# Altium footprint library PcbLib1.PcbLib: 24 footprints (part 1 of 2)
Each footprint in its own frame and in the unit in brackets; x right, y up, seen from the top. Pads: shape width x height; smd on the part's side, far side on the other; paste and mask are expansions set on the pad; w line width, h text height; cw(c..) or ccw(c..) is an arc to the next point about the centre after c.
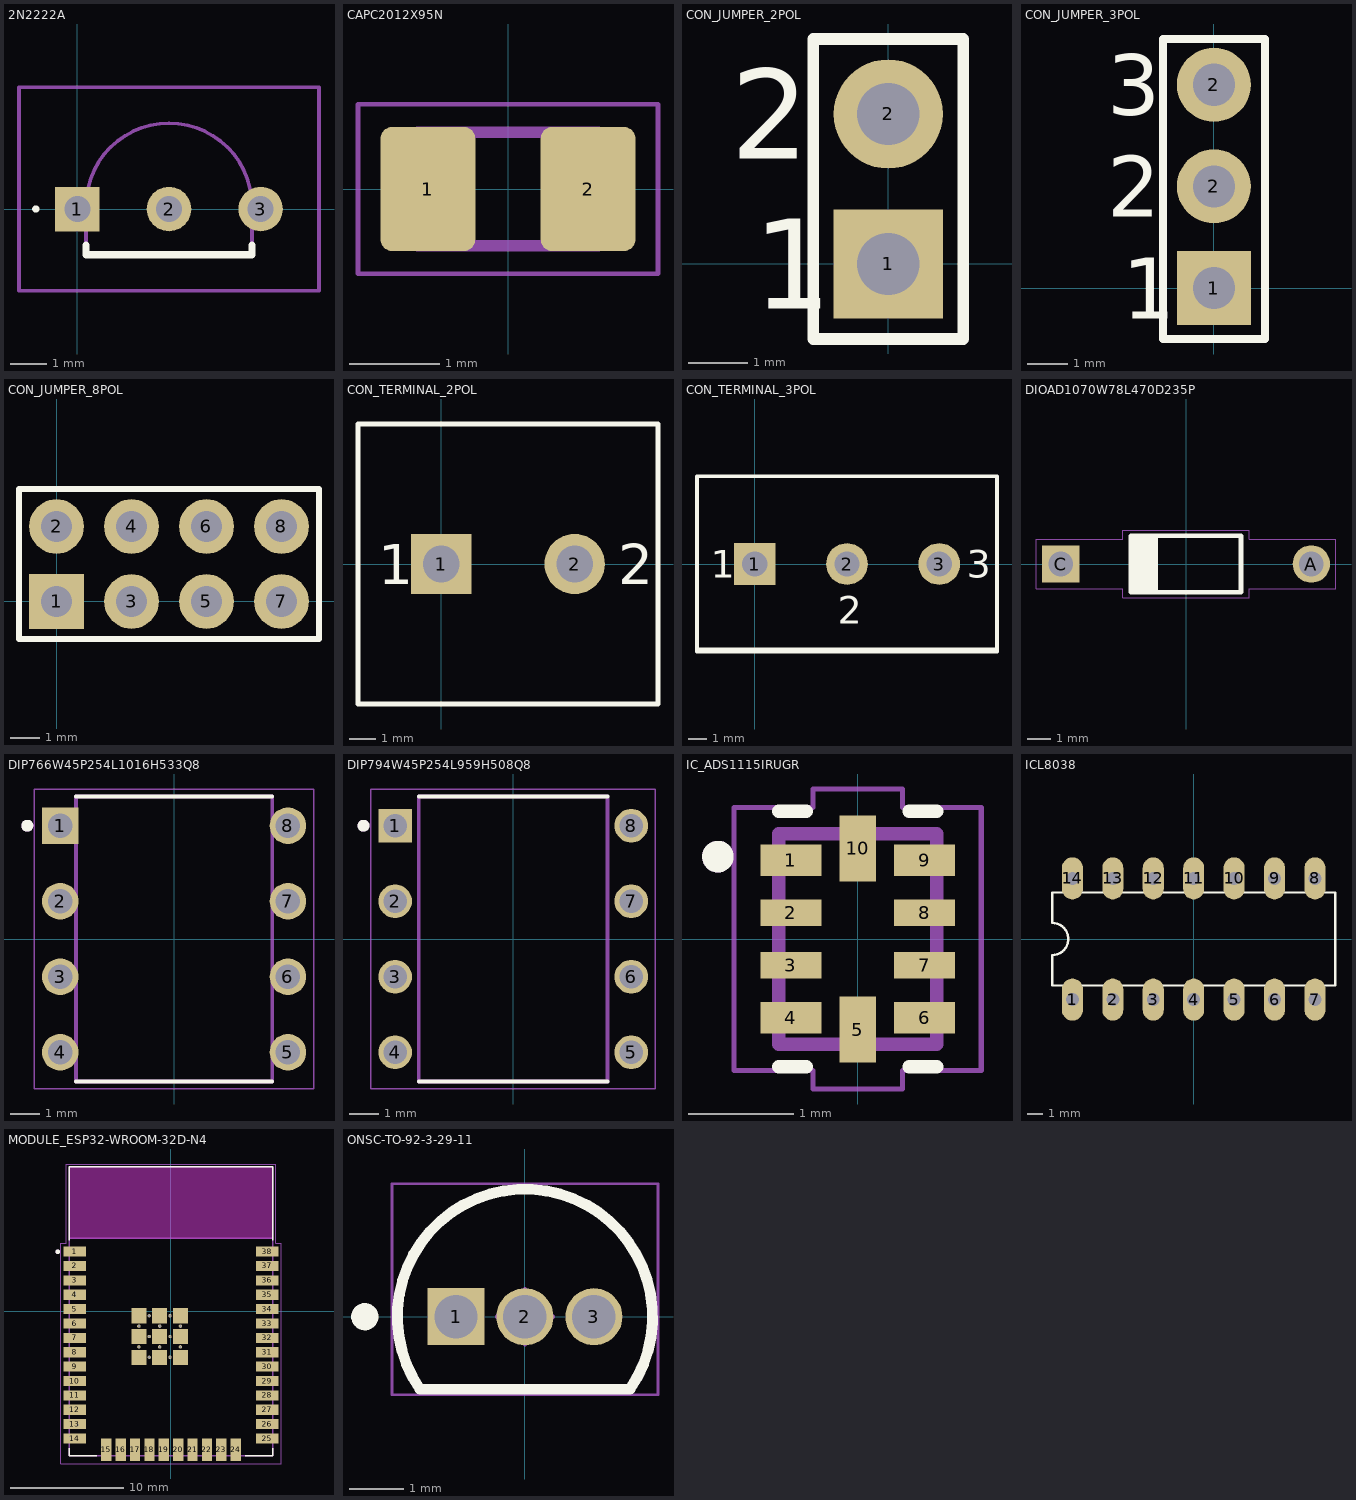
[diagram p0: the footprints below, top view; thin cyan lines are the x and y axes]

## 2N2222A [mm]
pads (3):
  rect 1.234x1.234 hole 0.72: 1(0,0)
  round 1.234 hole 0.72: 2(2.54,0) 3(5.08,0)
Top Overlay:
  lines w0.1: -1.2,0 cw(c-1.15,0) -1.1,0 cw(c-1.15,0) -1.2,0
  lines w0.2: 0.24,-1 0.24,-1.27 4.84,-1.27 4.84,-1
Mechanical 13:
  lines w0.1: 0.24,-1.27 0.24,0.08 cw(c2.54,0.08) 4.84,0.08 4.84,-1.27 0.24,-1.27
Mechanical 15:
  lines w0.1: -1.617,-2.27 -1.617,3.38 6.697,3.38 6.697,-2.27 -1.617,-2.27
3D body "2N2222A.stp": height 7.46, standoff -9.64, extent -0.2,-1.25 5.28,2.35

## CAPC2012X95N [mm]
pads (2):
  rrect25% 1.05x1.38 smd: 1(-0.888,0) 2(0.888,0)
Mechanical 13:
  lines w0.127: -1,-0.63 1,-0.63 1,0.63 -1,0.63 -1,-0.63
Mechanical 15:
  lines w0.05: -1.663,-0.94 1.663,-0.94 1.663,0.94 -1.663,0.94 -1.663,-0.94
3D body "step_temp.STEP": height 0.95, standoff 0, extent -1,-0.625 1,0.625

## CON_JUMPER_2POL [mm] "Jumper"
pads (2):
  rect 1.85x1.85 hole 1.05: 1(0,0)
  round 1.85 hole 1.05: 2(0,2.54)
Top Overlay:
  lines w0.2: -1.27,-1.27 1.27,-1.27 1.27,3.81 -1.27,3.81 -1.27,2.54 -1.27,-1.27
  text "1" at -2.286,-0.762 h1.52
  text "2" at -2.667,1.778 h1.52

## CON_JUMPER_3POL [mm] "Jumper"
pads (3):
  rect 1.85x1.85 hole 1.05: 1(0,0)
  round 1.85 hole 1.05: 2(0,2.54) 2(0,5.08)
Top Overlay:
  lines w0.2: -1.27,-1.27 1.27,-1.27 1.27,6.223 -1.27,6.223 -1.27,2.413 -1.27,-1.27
  text "3" at -2.667,4.318 h1.52
  text "1" at -2.286,-0.762 h1.52
  text "2" at -2.667,1.778 h1.52

## CON_JUMPER_8POL [mm] "Jumper"
pads (8):
  rect 1.85x1.85 hole 1.05: 1(0,0)
  round 1.85 hole 1.05: 2(0,2.54) 3(2.54,0) 4(2.54,2.54) 5(5.08,0) 6(5.08,2.54) 7(7.62,0) 8(7.62,2.54)
Top Overlay:
  lines w0.2: -1.27,-1.27 -1.27,3.81 8.89,3.81 8.89,-1.27 -1.27,-1.27

## CON_TERMINAL_2POL [mm] "Terminal Screw"
pads (2):
  rect 2.3x2.3 hole 1.4: 1(0,0)
  round 2.3 hole 1.4: 2(5.08,0)
Top Overlay:
  lines w0.2: -3.175,-5.334 -3.175,0 -3.175,5.334 8.255,5.334 8.255,-5.334 -3.175,-5.334
  text "2" at 6.731,-0.762 h1.52
  text "1" at -2.413,-0.762 h1.52

## CON_TERMINAL_3POL [mm] "Terminal Screw"
pads (3):
  rect 2.3x2.3 hole 1.4: 1(0,0)
  round 2.3 hole 1.4: 2(5.08,0) 3(10.16,0)
Top Overlay:
  lines w0.2: -3.048,-4.699 13.208,-4.699 ; -3.175,-4.826 -3.175,0 -3.175,4.826 13.335,4.826 13.335,-4.826 -3.175,-4.826
  text "3" at 11.684,-0.762 h1.52
  text "2" at 4.572,-3.302 h1.52
  text "1" at -2.413,-0.762 h1.52

## DIOAD1070W78L470D235P [mm]
pads (2):
  round 1.6 hole 1.05: A(5.35,0)
  rect 1.6x1.6 / inner round 1.6 / far side rect 1.6x1.6 hole 1.05: C(-5.35,0)
Top Overlay:
  region: -1.2,-1.202 -2.403,-1.202 -2.403,1.2 -1.2,1.2
  lines w0.2: -2.35,-1.2 -2.35,1.2 2.35,1.2 2.35,-1.2 -2.35,-1.2
Mechanical 15:
  lines w0.05: -6.4,-1.05 -6.4,1.05 -2.7,1.05 -2.7,1.45 2.7,1.45 2.7,1.05 6.4,1.05 6.4,-1.05 2.7,-1.05 2.7,-1.45 -2.7,-1.45 -2.7,-1.05 -6.4,-1.05
3D body "step_temp.STEP": height 2.7, standoff -21.05, extent -5.743,-1.35 5.743,1.35

## DIP766W45P254L1016H533Q8 [mm]
pads (8):
  rect 1.23x1.23 / inner round 1.23 / far side rect 1.23x1.23 hole 0.82: 1(-3.83,3.81)
  round 1.23 hole 0.82: 2(-3.83,1.27) 3(-3.83,-1.27) 4(-3.83,-3.81) 5(3.83,-3.81) 6(3.83,-1.27) 7(3.83,1.27) 8(3.83,3.81)
Top Overlay:
  circle w0.2: c-4.935,3.81 r0.1
  lines w0.127: -3.303,-4.795 3.303,-4.795 ; -3.303,4.795 3.303,4.795
Mechanical 13:
  circle w0.2: c-4.935,3.81 r0.1
  lines w0.127: -3.303,-4.795 3.303,-4.795 3.303,4.795 -3.303,4.795 -3.303,-4.795
Mechanical 15:
  lines w0.05: -4.695,-5.045 4.695,-5.045 4.695,5.045 -4.695,5.045 -4.695,-5.045
3D body "step_temp.STEP": height 5.33, standoff -3, extent -4.003,-4.94 4.003,4.94

## DIP794W45P254L959H508Q8 [mm]
pads (8):
  rect 1.13x1.13 / inner round 1.13 / far side rect 1.13x1.13 hole 0.78 mask+0.102: 1(-3.97,3.81)
  round 1.13 hole 0.78 mask+0.102: 2(-3.97,1.27) 3(-3.97,-1.27) 4(-3.97,-3.81) 5(3.97,-3.81) 6(3.97,-1.27) 7(3.97,1.27) 8(3.97,3.81)
Top Overlay:
  circle w0.2: c-5.035,3.81 r0.1
  lines w0.127: -3.175,-4.795 3.175,-4.795 ; -3.175,4.795 3.175,4.795
Mechanical 13:
  circle w0.2: c-5.035,3.81 r0.1
  lines w0.127: -3.175,-4.795 -3.175,4.795 3.175,4.795 3.175,-4.795 -3.175,-4.795
Mechanical 15:
  lines w0.05: -4.785,-5.045 -4.785,5.045 4.785,5.045 4.785,-5.045 -4.785,-5.045
3D body "step_temp.STEP": height 5.08, standoff -3.18, extent -4.095,-4.795 4.095,4.795

## IC_ADS1115IRUGR [mm]
pads (10):
  rect 0.58x0.3 smd paste-0.025: 1(-0.635,0.75) 4(-0.635,-0.75) 6(0.635,-0.75) 9(0.635,0.75)
  rect 0.58x0.25 smd paste-1: 2(-0.635,0.25) 3(-0.635,-0.25) 7(0.635,-0.25) 8(0.635,0.25)
  rect 0.35x0.63 smd paste-0.025: 5(0,-0.86) 10(0,0.86)
Top Overlay:
  circle w0.2: c-1.328,0.783 r0.05
  lines w0.127: -0.75,-1.213 -0.488,-1.213 ; -0.75,1.213 -0.488,1.213 ; 0.488,-1.213 0.75,-1.213 ; 0.488,1.213 0.75,1.213
Top Paste:
  region: -0.37,-0.375 -0.9,-0.375 -0.9,-0.125 -0.37,-0.125
  region: -0.37,0.125 -0.9,0.125 -0.9,0.375 -0.37,0.375
  region: 0.9,-0.375 0.37,-0.375 0.37,-0.125 0.9,-0.125
  region: 0.9,0.125 0.37,0.125 0.37,0.375 0.9,0.375
Mechanical 13:
  circle w0.2: c-1.328,0.783 r0.05
  lines w0.127: -0.75,-1 0.75,-1 0.75,1 -0.75,1 -0.75,-1
Mechanical 15:
  lines w0.05: -1.175,-1.25 -1.175,1.25 -0.425,1.25 -0.425,1.425 0.425,1.425 0.425,1.25 1.175,1.25 1.175,-1.25 0.425,-1.25 0.425,-1.425 -0.425,-1.425 -0.425,-1.25 -1.175,-1.25
3D body "step_temp.STEP": height 0.4, standoff 0, extent -0.75,-1 0.75,1

## ICL8038 [mil]
pads (14):
  oval 52x104 hole 32: 1(-300,-150) 2(-200,-150) 3(-100,-150) 4(0,-150) 5(100,-150) 6(200,-150) 7(300,-150) 8(300,150) 9(200,150) 10(100,150) 11(0,150) 12(-100,150) 13(-200,150) 14(-300,150)
Top Overlay:
  lines w6: -350,-115 -350,-40 ccw(c-350,0) -350,40 -350,115 350,115 350,-115 -350,-115

## MODULE_ESP32-WROOM-32D-N4 [mm]
height 3.2
pads (59):
  rect 2x0.9 smd: 1(-8.5,5.26) 2(-8.5,3.99) 3(-8.5,2.72) 4(-8.5,1.45) 5(-8.5,0.18) 6(-8.5,-1.09) 7(-8.5,-2.36) 8(-8.5,-3.63) 9(-8.5,-4.9) 10(-8.5,-6.17) 11(-8.5,-7.44) 12(-8.5,-8.71) 13(-8.5,-9.98) 14(-8.5,-11.25) 25(8.5,-11.25) 26(8.5,-9.98) 27(8.5,-8.71) 28(8.5,-7.44) 29(8.5,-6.17) 30(8.5,-4.9) 31(8.5,-3.63) 32(8.5,-2.36) 33(8.5,-1.09) 34(8.5,0.18) 35(8.5,1.45) 36(8.5,2.72) 37(8.5,3.99) 38(8.5,5.26)
  rect 0.9x2 smd: 15(-5.715,-12.25) 16(-4.445,-12.25) 17(-3.175,-12.25) 18(-1.905,-12.25) 19(-0.635,-12.25) 20(0.635,-12.25) 21(1.905,-12.25) 22(3.175,-12.25) 23(4.445,-12.25) 24(5.715,-12.25)
  rect 1.33x1.33 smd: 39_1(-2.835,-0.405) 39_2(-1,-0.405) 39_3(0.835,-0.405) 39_4(-2.835,-2.24) 39_5(-1,-2.24) 39_6(0.835,-2.24) 39_7(-2.835,-4.075) 39_8(-1,-4.075) 39_9(0.835,-4.075)
  round 0.3 hole 0.2: 39_10(-1.917,-0.405) 39_11(-0.082,-0.405) 39_12(-2.835,-1.322) 39_13(-1,-1.322) 39_14(0.835,-1.322) 39_15(-1.917,-2.24) 39_16(-0.082,-2.24) 39_17(-2.835,-3.157) 39_18(-1,-3.157) 39_19(0.835,-3.157) 39_20(-1.917,-4.075) 39_21(-0.082,-4.075)
Top Overlay:
  circle w0.2: c-10,5.25 r0.1
  lines w0.127: -9,-12.1 -9,-12.75 -6.55,-12.75 ; -9,6.25 -9,12.75 9,12.75 9,6.25 ; 6.55,-12.75 9,-12.75 9,-12.1
Keep-Out Layer:
  region: 9,6.45 -9,6.45 -9,12.75 9,12.75
Mechanical 13:
  circle w0.2: c-10,5.25 r0.1
  lines w0.127: -9,6.45 9,6.45 ; -9,6.45 -9,12.75 9,12.75 9,6.45 ; -9,6.45 -9,-12.75 9,-12.75 9,6.45
  text "ANTENNA" at -6,9 h1.78
Mechanical 15:
  lines w0.05: -9.75,-13.5 -9.75,6 -9.25,6 -9.25,13 9.25,13 9.25,6 9.75,6 9.75,-13.5 -9.75,-13.5
3D body "step_temp.STEP": height 3.25, standoff 0, extent -9,-12.75 9,12.75

## ONSC-TO-92-3-29-11 [mm] "TO, 3-Leads, Body Dia 4.7mm, Pitch 1.27mm"
height 7.87
pads (3):
  rect 1.05x1.05 hole 0.8: 1(-1.27,0)
  round 1.05 hole 0.8: 2(0,0) 3(1.27,0)
Top Overlay:
  circle w0.25: c-2.95,0 r0.125
  lines w0.2: -1.934,-1.335 cw(c0,0) 1.934,-1.335 -1.934,-1.335
Mechanical 13:
  lines w0.1: -1.934,-1.335 cw(c0,0) 1.934,-1.335 -1.934,-1.335
Mechanical 15:
  lines w0.05: -2.45,-1.435 2.45,-1.435 2.45,2.45 -2.45,2.45 -2.45,-1.435
  lines w0.1: -0.5,0 0.5,0 ; 0,-0.5 0,0.5
3D body: height 7.87, standoff 2.54, extent -2.349,-1.334 2.357,2.359

## PCBComponent_1 [mm]

## PCBComponent_1 - duplicate [mm]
